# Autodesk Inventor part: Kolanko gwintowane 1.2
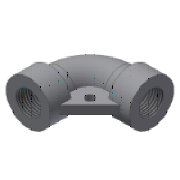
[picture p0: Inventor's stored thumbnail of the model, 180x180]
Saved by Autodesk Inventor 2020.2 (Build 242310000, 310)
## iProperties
Manager: www.cadconsulting.pl
Company: Fabian Stasiak CAD Consulting
Created: 2014-08
Part Number: Kolanko gwintowane 1.2
Material: Ogólny
Document SubType Name: Modeling
Designer: F.Stasiak
Language: pl-PL
Size Designation: 1/2
Categories: <MemberInstance><Categories><Category DisplayName="Rury cienko- i grubościenne" InternalName="4347fa0f-2144-441d-94cd-e3e15c92b736" Mnemonic="TUBEANDPIPE"><Cate
Density: 1 g/cm^3
Appearance: Domyślna
Catalog Web Link: www.expertbooks.pl
IsCustomPart: 0
Author: F.Stasiak
Subject: Zbiór ćwiczeń. Autodesk Inventor 2020. Kurs Professional
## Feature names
1. Przeciągnięcie1
2. Wyciągnięcie proste1 [Extrusion]
3. Wyciągnięcie proste2 [Extrusion]
4. Wyciągnięcie proste5 [Extrusion]
## Parameters: d0 = 45.7835 mm, d1 = 45.7835 mm, d2 = 22.89175 mm, d4 = 0, d5 = 0, d6 = 33.02 mm, d7 = 18.3134 mm, d9 = 15.748 mm, d10 = 0, d11 = 33.02 mm, d12 = 15.748 mm, d13 = 0, d19 = 19.8628 mm, d20 = 0, d21 = 19.8628 mm, d22 = 0, ID = 18.3134 mm, OD = 33.02 mm, GL = 15.748 mm, G = 3.175 mm, d23 = 3.175 mm, d24 = 6.35 mm, d26 = 6.35 mm, d27 = 0
